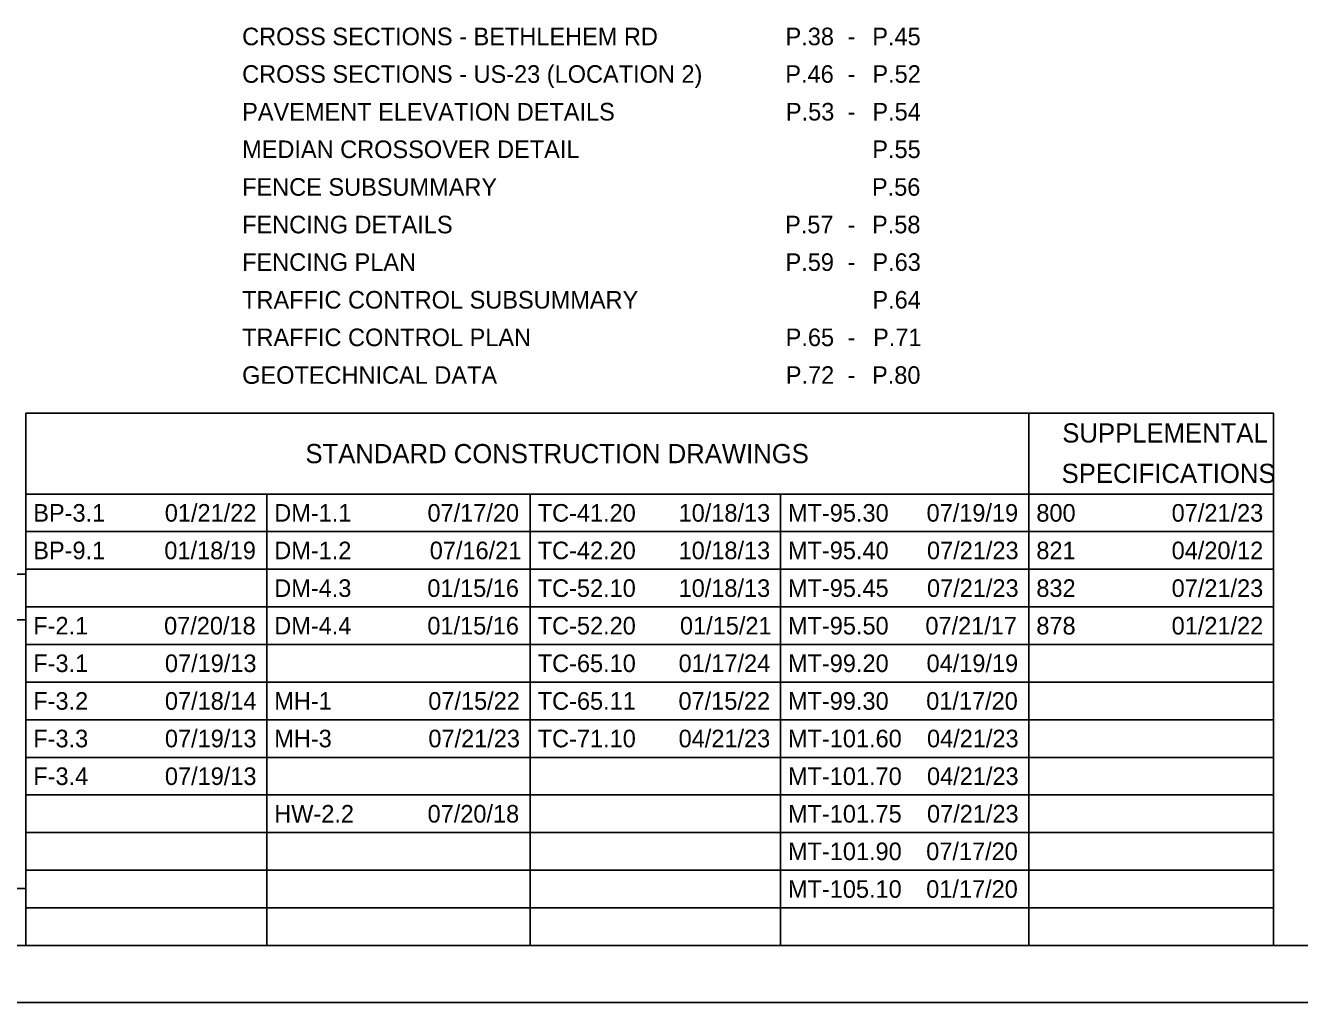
# Model space of a CAD drawing. Extents: x 0 to 34, y 0 to 22.
# Drawn here: x 12.03 to 23.18, y 0 to 8.56 of the extents above; entities that cross this region are included whole.
import ezdxf

# ---------------------------------------------------------------- set-up
doc = ezdxf.new("R2010")
doc.units = 0
for name, color, linetype in [('SH_Border', 7, 'Continuous'), ('SH_Cut_Line', 7, 'Continuous'), ('SH_Data', 7, 'Continuous'), ('SH_Text', 7, 'Continuous')]:
    doc.layers.add(name, color=color, linetype=linetype)

msp = doc.modelspace()

# ---------------------------------------------------------------- linework, layer by layer
at = {"layer": 'SH_Border'}
msp.add_lwpolyline([(1.5, 21.5), (33.5, 21.5), (33.5, 0.5), (1.5, 0.5)], close=True, dxfattribs=at)
at = {"layer": 'SH_Cut_Line'}
msp.add_lwpolyline([(0, 0), (34, 0), (34, 22), (0, 22)], close=True, dxfattribs=at)
at = {"layer": 'SH_Data'}
for p, q in [((9.234, 3.75), (12.034, 3.75)), ((12.034, 3.75), (12.034, 0.5)), ((9.234, 3.35), (12.034, 3.35)), ((9.234, 0.5), (12.034, 0.5))]:
    msp.add_line(p, q, dxfattribs=at)
msp.add_lwpolyline([(9.234, 0.5), (9.234, 1), (12.034, 1), (12.034, 0.5)], close=True, dxfattribs=at)
at = {"layer": 'SH_Text'}
for p, q in [((12.034, 5.161), (22.954, 5.161)), ((12.034, 5.161), (12.034, 0.5)), ((20.812, 5.161), (20.812, 0.5)), ((22.954, 5.161), (22.954, 0.5)), ((12.034, 4.453), (22.954, 4.453)), ((14.142, 4.453), (14.142, 0.5)), ((16.448, 4.453), (16.448, 0.5)), ((18.638, 4.453), (18.638, 0.5)), ((12.034, 4.124), (22.954, 4.124)), ((12.034, 3.794), (22.954, 3.794)), ((12.034, 3.465), (22.954, 3.465)), ((12.034, 3.135), (22.954, 3.135)), ((12.034, 2.806), (22.954, 2.806)), ((12.034, 2.476), (22.954, 2.476)), ((12.034, 2.147), (22.954, 2.147)), ((12.034, 1.818), (22.954, 1.818)), ((12.034, 1.488), (22.954, 1.488)), ((12.034, 1.159), (22.954, 1.159)), ((12.034, 0.829), (22.954, 0.829)), ((12.034, 0.5), (22.954, 0.5))]:
    msp.add_line(p, q, dxfattribs=at)

# ---------------------------------------------------------------- texts
for s, height, p in [('CROSS SECTIONS - BETHLEHEM RD', 0.154, (13.927, 8.383)), ('P.38', 0.154, (18.683, 8.383)), ('P.45', 0.154, (19.442, 8.383)), ('-', 0.154, (19.225, 8.383)), ('CROSS SECTIONS - US-23 (LOCATION 2)', 0.154, (13.927, 8.054)), ('P.46', 0.154, (18.681, 8.054)), ('P.52', 0.154, (19.443, 8.054)), ('-', 0.154, (19.225, 8.054)), ('PAVEMENT ELEVATION DETAILS', 0.154, (13.927, 7.724)), ('P.53', 0.154, (18.686, 7.724)), ('P.54', 0.154, (19.443, 7.724)), ('-', 0.154, (19.225, 7.724)), ('MEDIAN CROSSOVER DETAIL', 0.154, (13.927, 7.395)), ('P.55', 0.154, (19.442, 7.395)), ('FENCE SUBSUMMARY', 0.154, (13.927, 7.065)), ('P.56', 0.154, (19.439, 7.065)), ('FENCING DETAILS', 0.154, (13.927, 6.736)), ('P.57', 0.154, (18.679, 6.736)), ('-', 0.154, (19.225, 6.736)), ('P.58', 0.154, (19.44, 6.736)), ('FENCING PLAN', 0.154, (13.927, 6.407)), ('P.59', 0.154, (18.683, 6.407)), ('-', 0.154, (19.225, 6.407)), ('P.63', 0.154, (19.443, 6.407)), ('TRAFFIC CONTROL SUBSUMMARY', 0.154, (13.927, 6.077)), ('P.64', 0.154, (19.443, 6.077)), ('TRAFFIC CONTROL PLAN', 0.154, (13.927, 5.748)), ('P.65', 0.154, (18.684, 5.748)), ('-', 0.154, (19.225, 5.748)), ('P.71', 0.154, (19.449, 5.748)), ('GEOTECHNICAL DATA', 0.154, (13.927, 5.418)), ('P.72', 0.154, (18.685, 5.418)), ('-', 0.154, (19.225, 5.418)), ('P.80', 0.154, (19.44, 5.418)), ('SUPPLEMENTAL', 0.168, (21.105, 4.904)), ('STANDARD CONSTRUCTION DRAWINGS', 0.168, (14.481, 4.723)), ('SPECIFICATIONS', 0.168, (21.099, 4.55)), ('BP-3.1', 0.154, (12.099, 4.211)), ('01/21/22', 0.154, (13.25, 4.211)), ('DM-1.1', 0.154, (14.208, 4.211)), ('07/17/20', 0.154, (15.549, 4.211)), ('TC-41.20', 0.154, (16.514, 4.211)), ('10/18/13', 0.154, (17.747, 4.211)), ('MT-95.30', 0.154, (18.704, 4.211)), ('07/19/19', 0.154, (19.917, 4.211)), ('800', 0.154, (20.878, 4.211)), ('07/21/23', 0.154, (22.062, 4.211)), ('BP-9.1', 0.154, (12.099, 3.882)), ('01/18/19', 0.154, (13.246, 3.882)), ('DM-1.2', 0.154, (14.208, 3.882)), ('07/16/21', 0.154, (15.569, 3.882)), ('TC-42.20', 0.154, (16.514, 3.882)), ('10/18/13', 0.154, (17.747, 3.882)), ('MT-95.40', 0.154, (18.704, 3.882)), ('07/21/23', 0.154, (19.921, 3.882)), ('821', 0.154, (20.878, 3.882)), ('04/20/12', 0.154, (22.062, 3.882)), ('DM-4.3', 0.154, (14.208, 3.552)), ('01/15/16', 0.154, (15.548, 3.552)), ('TC-52.10', 0.154, (16.514, 3.552)), ('10/18/13', 0.154, (17.747, 3.552)), ('MT-95.45', 0.154, (18.704, 3.552)), ('07/21/23', 0.154, (19.921, 3.552)), ('832', 0.154, (20.878, 3.552)), ('07/21/23', 0.154, (22.062, 3.552)), ('F-2.1', 0.154, (12.099, 3.223)), ('07/20/18', 0.154, (13.244, 3.223)), ('DM-4.4', 0.154, (14.208, 3.223)), ('01/15/16', 0.154, (15.548, 3.223)), ('TC-52.20', 0.154, (16.514, 3.223)), ('01/15/21', 0.154, (17.759, 3.223)), ('MT-95.50', 0.154, (18.704, 3.223)), ('07/21/17', 0.154, (19.907, 3.223)), ('878', 0.154, (20.878, 3.223)), ('01/21/22', 0.154, (22.062, 3.223)), ('F-3.1', 0.154, (12.099, 2.894)), ('07/19/13', 0.154, (13.251, 2.894)), ('TC-65.10', 0.154, (16.514, 2.894)), ('01/17/24', 0.154, (17.747, 2.894)), ('MT-99.20', 0.154, (18.704, 2.894)), ('04/19/19', 0.154, (19.917, 2.894)), ('F-3.2', 0.154, (12.099, 2.564)), ('07/18/14', 0.154, (13.251, 2.564)), ('MH-1', 0.154, (14.208, 2.564)), ('07/15/22', 0.154, (15.556, 2.564)), ('TC-65.11', 0.154, (16.514, 2.564)), ('07/15/22', 0.154, (17.746, 2.564)), ('MT-99.30', 0.154, (18.704, 2.564)), ('01/17/20', 0.154, (19.914, 2.564)), ('F-3.3', 0.154, (12.099, 2.235)), ('07/19/13', 0.154, (13.251, 2.235)), ('MH-3', 0.154, (14.208, 2.235)), ('07/21/23', 0.154, (15.557, 2.235)), ('TC-71.10', 0.154, (16.514, 2.235)), ('04/21/23', 0.154, (17.747, 2.235)), ('MT-101.60', 0.154, (18.704, 2.235)), ('04/21/23', 0.154, (19.921, 2.235)), ('F-3.4', 0.154, (12.099, 1.905)), ('07/19/13', 0.154, (13.251, 1.905)), ('MT-101.70', 0.154, (18.704, 1.905)), ('04/21/23', 0.154, (19.921, 1.905)), ('HW-2.2', 0.154, (14.208, 1.576)), ('07/20/18', 0.154, (15.55, 1.576)), ('MT-101.75', 0.154, (18.704, 1.576)), ('07/21/23', 0.154, (19.921, 1.576)), ('MT-101.90', 0.154, (18.704, 1.247)), ('07/17/20', 0.154, (19.914, 1.247)), ('MT-105.10', 0.154, (18.704, 0.917)), ('01/17/20', 0.154, (19.914, 0.917))]:
    msp.add_text(s, height=height, dxfattribs=at).set_placement(p)

doc.saveas('drawing.dxf')
